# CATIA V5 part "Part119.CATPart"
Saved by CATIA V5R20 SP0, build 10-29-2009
Part number: FA 084700-3
Revision: ANY
Definition: UNKNOWN
Nomenclature: FA 084700-3
Source: Unknown
Bounding box of the stored display mesh (mm): x -2.687 to 2.687, y -2.475 to 2.475, z -2.5 to 2.5
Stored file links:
  C:\Users\Utente\Desktop\IO LAVORO\3D X SITO CF\CUMSA\3D files FA\FA 084700\Part119.CATPart

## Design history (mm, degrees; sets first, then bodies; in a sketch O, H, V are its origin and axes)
Body1 "Chaflán4" (main body)
  Solid1: solid without history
